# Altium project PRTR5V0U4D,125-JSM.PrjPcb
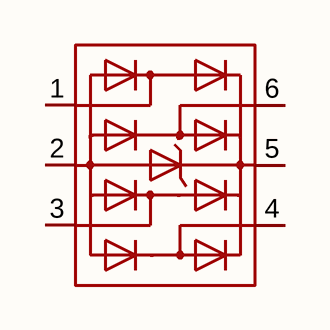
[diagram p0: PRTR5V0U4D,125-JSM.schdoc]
1 sheet, 1 parts. Net scope: global (net labels, ports and power ports of the same name join across sheets).

## Sheet PRTR5V0U4D,125-JSM.schdoc
size 127 x 101 mm

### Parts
D?  prtr5v0u4d,125-jsm  [SOT-23-6_L2.9-W1.6-P0.95-LS2.8-BR-3]  (value not drawn)

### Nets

Not connected (* = marked no-connect by the designer): D? 1(ESD3) 2(GND) 3(ESD4) 4(ESD1) 5(VCC) 6(ESD2)

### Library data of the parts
D? = prtr5v0u4d,125-jsm: 极性:-;反向截止电压(Vrwm):5V;钳位电压:18.5V；18V;峰值脉冲电流(Ipp):11A@8/20us；3.5A@8/20us;峰值脉冲功率(Ppp):200W@8/20us；54W@8/20us;击穿电压(VBR):7.5V;; Manufacturer: JSMSEMI(杰盛微); AddInBom: yes; ModelId: eb4edb93ea2445c79c7148010394783b; ModelTransform: 110.236,114.19371,0,0,0,0,0,0,0; Reverse Stand-Off Voltage (Vrwm): 5V; Voltage - Breakdown: 7.5V; Reverse Leakage Current (Ir): 500nA; level of protection: IEC 61000-4-5；IEC 61000-4-2; Type: TVS; Junction Capacitance: 0.6pF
